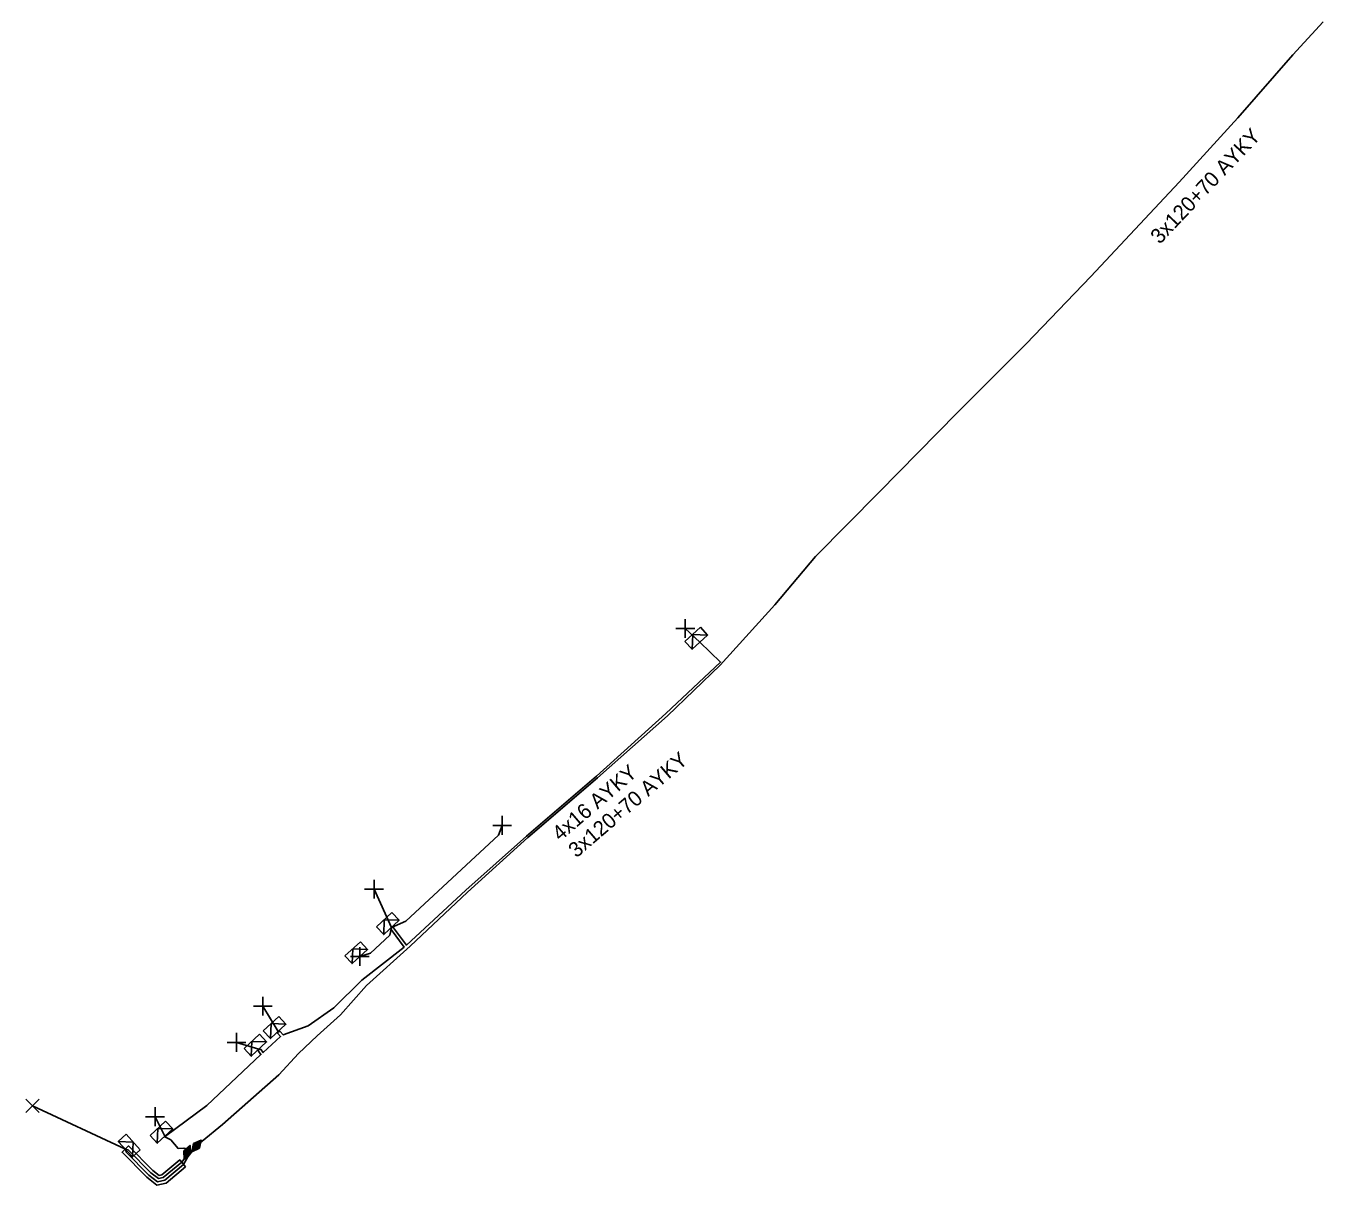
# Model space of a CAD drawing. Extents: x -544780 to -541582, y -1198995 to -1196551.
# Drawn here: x -543975.2 to -543888.9, y -1197509.4 to -1197432.3 of the extents above; entities that cross this region are included whole.
import ezdxf

# ---------------------------------------------------------------- set-up
doc = ezdxf.new("R2010")
doc.units = 0
for name, color, linetype in [('Vrstva 1', 7, 'Continuous'), ('Vrstva 19', 7, 'Continuous'), ('Vrstva 20', 7, 'Continuous'), ('Vrstva 31', 7, 'Continuous'), ('Vrstva 34', 7, 'Continuous'), ('Vrstva 4', 7, 'Continuous'), ('Vrstva 5', 7, 'Continuous'), ('Vrstva 52', 7, 'Continuous'), ('Vrstva 59', 7, 'Continuous'), ('Vrstva 6', 7, 'Continuous'), ('Vrstva 9', 7, 'Continuous')]:
    doc.layers.add(name, color=color, linetype=linetype)

# ---------------------------------------------------------------- blocks, each defined once
blk = doc.blocks.new('NN870')
at = {"layer": 'Vrstva 4'}
for points in [[(0, -0.251), (0.5, 0.001), (0, 0.249), (-0.5, 0.001), (0, -0.251)], [(0.37, -0.003), (0, 0.186), (-0.362, 0.001), (0, -0.188), (0.37, -0.003)], [(0.245, -0.003), (0, 0.123), (-0.252, -0.003), (0, -0.125), (0.245, -0.003)], [(0.122, -0.003), (0, 0.06), (-0.13, -0.003), (0, -0.062), (0.122, -0.003)]]:
    blk.add_lwpolyline(points, dxfattribs=at)
blk = doc.blocks.new('NN800')
at = {"layer": 'Vrstva 1'}
for points in [[(-0.442, 0.442), (0.442, -0.442)], [(-0.442, -0.442), (0.442, 0.442)]]:
    blk.add_lwpolyline(points, dxfattribs=at)
blk = doc.blocks.new('NN630')
at = {"layer": 'Vrstva 9'}
for points in [[(-0.003, -0.7), (-0.703, 0)], [(-0.703, -0.7), (-0.703, 0), (0.697, 0), (0.697, -0.7)], [(-0.703, -0.7), (0.697, -0.7)], [(-0.003, -0.7), (0.697, 0)]]:
    blk.add_lwpolyline(points, dxfattribs=at)

msp = doc.modelspace()

# ---------------------------------------------------------------- linework, layer by layer
at = {"layer": 'Vrstva 20'}
msp.add_lwpolyline([(-543964.548, -1197508.221), (-543965.844, -1197509.297), (-543966.451, -1197509.433), (-543967.129, -1197508.915), (-543968.764, -1197507.25), (-543968.336, -1197506.83), (-543966.731, -1197508.465), (-543966.309, -1197508.787), (-543966.116, -1197508.743), (-543964.932, -1197507.759)], close=True, dxfattribs=at)
at = {"layer": 'Vrstva 5'}
for points in [[(-543888.89, -1197432.05), (-543890.9, -1197434.26), (-543894.56, -1197438.44), (-543898.47, -1197442.72), (-543904.34, -1197448.99), (-543908.64, -1197453.48), (-543913.23, -1197458.07), (-543918.42, -1197463.34), (-543922.64, -1197467.63), (-543925.35, -1197470.84), (-543928.98, -1197474.85), (-543932.5, -1197478.22), (-543937.14, -1197482.35), (-543941.78, -1197486.32), (-543945.8, -1197489.96), (-543949.6, -1197493.55), (-543952.51, -1197496.15), (-543954.25, -1197498.1), (-543955.79, -1197499.51), (-543957.03, -1197500.69), (-543958.34, -1197502.1), (-543962.08, -1197505.4), (-543963.438, -1197506.518), (-543963.82, -1197506.83)], [(-543958.392, -1197499.214), (-543958.258, -1197499.213), (-543958.048, -1197499.443), (-543956.4, -1197498.85), (-543954.69, -1197497.64), (-543952.82, -1197495.8), (-543950.009, -1197493.602), (-543950.869, -1197492.444), (-543950.855, -1197492.295), (-543950.709, -1197492.324), (-543949.856, -1197493.472), (-543945.9, -1197489.82), (-543941.88, -1197486.23), (-543937.21, -1197482.24), (-543932.6, -1197478.07), (-543928.96, -1197474.65), (-543930.343, -1197473.321)], [(-543965.914, -1197506.179), (-543965.88, -1197506.17), (-543963.14, -1197504.14), (-543959.533, -1197500.759), (-543959.694, -1197500.527), (-543959.667, -1197500.391), (-543959.53, -1197500.413), (-543959.386, -1197500.622), (-543958.224, -1197499.548), (-543958.406, -1197499.347), (-543958.392, -1197499.214)], [(-543964.44, -1197507.26), (-543964.41, -1197507.05), (-543964.66, -1197506.98), (-543965.046, -1197507.001), (-543965.53, -1197506.42), (-543965.93, -1197506.22), (-543965.914, -1197506.179)], [(-543963.82, -1197506.83), (-543964.4, -1197507.561), (-543964.676, -1197508.067), (-543965.935, -1197509.112), (-543966.404, -1197509.218), (-543966.996, -1197508.765), (-543968.491, -1197507.242), (-543968.55, -1197507.04), (-543968.353, -1197507.098), (-543966.864, -1197508.615), (-543966.356, -1197509.002), (-543966.025, -1197508.928), (-543964.804, -1197507.913), (-543964.578, -1197507.596), (-543964.44, -1197507.26)]]:
    msp.add_lwpolyline(points, dxfattribs=at)
at = {"layer": 'Vrstva 52'}
for points in [[(-543950.855, -1197492.295), (-543949.885, -1197491.881), (-543943.735, -1197486.156), (-543943.493, -1197485.505)], [(-543950.855, -1197492.295), (-543950.969, -1197492.817), (-543952.255, -1197494.005), (-543952.96, -1197494.236)]]:
    msp.add_lwpolyline(points, dxfattribs=at)
at = {"layer": 'Vrstva 59'}
for points in [[(-543930.343, -1197473.321), (-543931.306, -1197472.418)], [(-543950.855, -1197492.295), (-543952.012, -1197489.755)], [(-543958.392, -1197499.214), (-543959.403, -1197497.528)], [(-543959.667, -1197500.391), (-543961.153, -1197499.942)], [(-543968.55, -1197507.04), (-543974.721, -1197504.16)], [(-543965.914, -1197506.179), (-543966.579, -1197504.888)]]:
    msp.add_lwpolyline(points, dxfattribs=at)

# ---------------------------------------------------------------- block references
at = {"layer": 'Vrstva 19'}
for p, rotation in [((-543964.44, -1197507.26), 67.65935203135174), ((-543963.82, -1197506.83), 51.581944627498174)]:
    msp.add_blockref('NN870', p, dxfattribs=dict(at, rotation=rotation))
at = {"layer": 'Vrstva 31'}
for p, rotation in [((-543930.343, -1197473.321), -137.2491777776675), ((-543950.855, -1197492.295), -137.02896105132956), ((-543952.96, -1197494.235), -137.53214727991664), ((-543958.392, -1197499.214), -137.49265822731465), ((-543959.667, -1197500.391), -136.68463331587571), ((-543965.914, -1197506.179), -137.2423638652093), ((-543968.55, -1197507.04), 132.5104471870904)]:
    msp.add_blockref('NN630', p, dxfattribs=dict(at, rotation=rotation))
at = {"layer": 'Vrstva 34', "rotation": 45}
for p in [(-543931.306, -1197472.417), (-543943.493, -1197485.505), (-543952.012, -1197489.755), (-543952.96, -1197494.236), (-543959.403, -1197497.528), (-543961.153, -1197499.942), (-543966.579, -1197504.888)]:
    msp.add_blockref('NN800', p, dxfattribs=at)
at = {"layer": 'Vrstva 34'}
msp.add_blockref('NN800', (-543974.721, -1197504.16), dxfattribs=at)

# ---------------------------------------------------------------- texts
at = {"layer": 'Vrstva 6'}
for s, rotation, p in [('3x120+70 AYKY', 46.593, (-543899.748, -1197446.892)), ('3x120+70 AYKY', 40.55, (-543938.551, -1197487.707)), ('4x16 AYKY', 40.51, (-543939.63, -1197486.592))]:
    msp.add_text(s, height=1, rotation=rotation, dxfattribs=at).set_placement(p)

doc.saveas('drawing.dxf')
